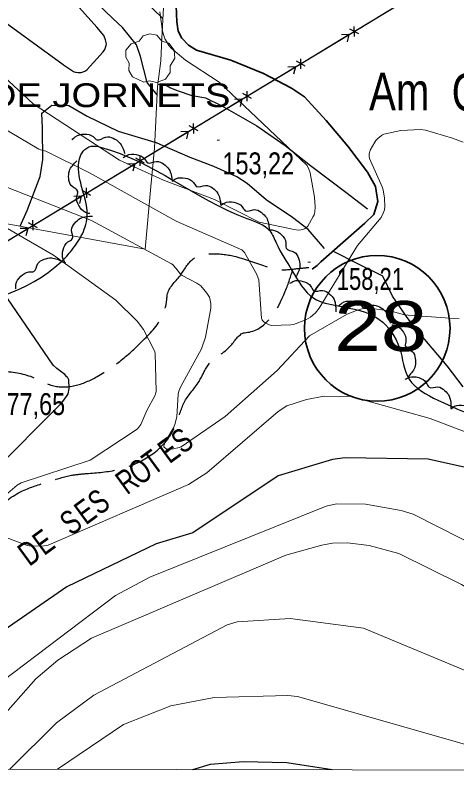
# Model space of a CAD drawing. Extents: x 483840 to 488445, y 4386047 to 4389027.
# Drawn here: x 484181.3 to 484357.8, y 4386444.9 to 4386749.2 of the extents above; entities that cross this region are included whole.
import ezdxf
from ezdxf.enums import TextEntityAlignment as Align

# ---------------------------------------------------------------- set-up
doc = ezdxf.new("R2010")
doc.units = 0
doc.header["$LTSCALE"] = 4
doc.linetypes.add('LONG_DASHED', pattern=[7.5, 6, -1.5])
for name, color, linetype, lineweight in [('1', 7, 'Continuous', 13), ('13', 7, 'Continuous', 25), ('25', 7, 'LONG_DASHED', 25), ('27', 7, 'Continuous', 25), ('29', 7, 'Continuous', 13), ('38', 7, 'Continuous', 25), ('43', 7, 'Continuous', 25), ('51', 7, 'Continuous', 13), ('6', 7, 'Continuous', 35), ('7', 7, 'Continuous', 13), ('8', 7, 'Continuous', 25), ('9', 7, 'Continuous', 13)]:
    doc.layers.add(name, color=color, linetype=linetype, lineweight=lineweight)
doc.layers.add('31', color=7, linetype='Continuous')
doc.layers.add('5', color=7, linetype='Continuous')

msp = doc.modelspace()

# ---------------------------------------------------------------- linework, layer by layer
at = {"layer": '1'}
msp.add_lwpolyline([(484110.5, 4388760.3), (487685.8, 4388753.5), (487681.9, 4386441.2), (484105.5, 4386448.1)], close=True, dxfattribs=at)
at = {"layer": '25'}
for points in [[(484238.11, 4386717.41), (484234.09, 4386722.37), (484231.36, 4386732.68), (484229.87, 4386737.33), (484224.27, 4386744.27), (484220.31, 4386747.9), (484213.85, 4386754.21)], [(484232.46, 4386755.62), (484240.38, 4386747.89)], [(484238.38, 4386721.61), (484241.44, 4386721.36), (484243.45, 4386720.19), (484246.51, 4386718.94), (484251.48, 4386717.25), (484257.46, 4386716.23), (484263.97, 4386712.97), (484277.97, 4386704.98), (484289.18, 4386697.18), (484299.41, 4386689.13), (484313.97, 4386678.15), (484322.22, 4386671.82)], [(484183.27, 4386664.84), (484186.06, 4386671.21), (484191.27, 4386684.79), (484192.36, 4386691.58), (484192.2, 4386704.04), (484192.02, 4386710.01), (484196, 4386713.23), (484202.78, 4386713.14), (484210.15, 4386708.79), (484222.46, 4386702.83), (484237.13, 4386698.45)], [(484304.96, 4386655.92), (484298.47, 4386663.58), (484292.2, 4386668.41), (484281.64, 4386675.45), (484274.11, 4386681.95), (484269.92, 4386684.63), (484260.73, 4386688.69), (484251.28, 4386692.36), (484237.13, 4386698.45)], [(484360.41, 4386600.63), (484354.02, 4386609.13), (484342.83, 4386622.33), (484338.08, 4386628.43), (484332.17, 4386636.95), (484328.3, 4386644.98), (484318.53, 4386649.68), (484308.26, 4386654.85)]]:
    msp.add_lwpolyline(points, dxfattribs=at)
at = {"layer": '27'}
for points in [[(484204.1, 4386699.4), (484205.36, 4386700.65), (484209, 4386701.71), (484212.54, 4386700.67), (484214.12, 4386699.36), (484217.48, 4386700.52), (484220.43, 4386700.06), (484222.95, 4386698.39), (484225.09, 4386693.91)], [(484109.46, 4386593.06), (484150.94, 4386626.49), (484199.73, 4386650.7), (484203.95, 4386655.31), (484208.18, 4386661.85), (484210.1, 4386669.53), (484207.03, 4386691.82), (484208.56, 4386694.9), (484211.64, 4386696.82), (484215.48, 4386696.43), (484273.86, 4386668), (484283.08, 4386663), (484285.77, 4386658), (484291.92, 4386647.24), (484300.75, 4386636.1), (484310.35, 4386633.02), (484326.87, 4386627.64), (484334.94, 4386616.12), (484338.78, 4386603.82), (484350.3, 4386595.36), (484426.74, 4386553.47), (484429.82, 4386547.71), (484429.82, 4386545.79), (484429.82, 4386540.02), (484422.52, 4386535.03), (484386.41, 4386496.98), (484386.03, 4386493.91), (484387.56, 4386490.45), (484397.55, 4386477), (484431.35, 4386465.85), (484447.87, 4386459.7), (484460.55, 4386449.71), (484465.92, 4386445.87)], [(484224.46, 4386692.17), (484225.93, 4386693.16), (484229.71, 4386693.52), (484232.99, 4386691.84), (484234.3, 4386690.25), (484237.82, 4386690.77), (484240.63, 4386689.76), (484242.79, 4386687.65), (484244.06, 4386682.86)], [(484211.11, 4386669.9), (484209.41, 4386670.41), (484206.74, 4386673.11), (484205.96, 4386676.71), (484206.36, 4386678.73), (484203.73, 4386681.13), (484202.73, 4386683.94), (484202.99, 4386686.95), (484205.9, 4386690.97)], [(484244.07, 4386682.88), (484245.56, 4386683.85), (484249.34, 4386684.12), (484252.59, 4386682.38), (484253.87, 4386680.77), (484257.4, 4386681.21), (484260.19, 4386680.15), (484262.31, 4386677.99), (484263.48, 4386673.17)], [(484263.48, 4386673.18), (484264.97, 4386674.15), (484268.76, 4386674.43), (484272.01, 4386672.68), (484273.28, 4386671.07), (484276.81, 4386671.51), (484279.6, 4386670.45), (484281.72, 4386668.3), (484282.89, 4386663.48)], [(484201.42, 4386650.13), (484200.54, 4386651.67), (484200.49, 4386655.47), (484202.43, 4386658.61), (484204.11, 4386659.79), (484203.89, 4386663.33), (484205.11, 4386666.06), (484207.39, 4386668.04), (484212.27, 4386668.92)], [(484282.73, 4386663.35), (484284.51, 4386663.33), (484287.8, 4386661.45), (484289.53, 4386658.18), (484289.69, 4386656.14), (484292.86, 4386654.53), (484294.59, 4386652.1), (484295.15, 4386649.13), (484293.43, 4386644.47)], [(484181.61, 4386639.79), (484181.64, 4386641.56), (484183.51, 4386644.86), (484186.77, 4386646.59), (484188.82, 4386646.75), (484190.42, 4386649.93), (484192.85, 4386651.66), (484195.82, 4386652.22), (484200.48, 4386650.51)], [(484291.08, 4386642.08), (484292.65, 4386642.91), (484296.45, 4386642.84), (484299.53, 4386640.81), (484300.65, 4386639.09), (484304.2, 4386639.21), (484306.89, 4386637.9), (484308.8, 4386635.56), (484309.53, 4386630.66)], [(484310.61, 4386633.01), (484311.95, 4386634.18), (484315.65, 4386635), (484319.12, 4386633.74), (484320.61, 4386632.33), (484324.04, 4386633.27), (484326.95, 4386632.63), (484329.36, 4386630.8), (484331.21, 4386626.19)], [(484331.9, 4386625.49), (484333.64, 4386625.1), (484336.49, 4386622.6), (484337.52, 4386619.06), (484337.27, 4386617.02), (484340.05, 4386614.81), (484341.25, 4386612.08), (484341.2, 4386609.05), (484338.59, 4386604.84)], [(484337.24, 4386603.7), (484338.83, 4386604.51), (484342.62, 4386604.39), (484345.67, 4386602.31), (484346.77, 4386600.57), (484350.32, 4386600.64), (484352.99, 4386599.29), (484354.87, 4386596.93), (484355.53, 4386592.01)], [(484355.5, 4386591.93), (484356.98, 4386592.9), (484360.76, 4386593.19), (484364.02, 4386591.46), (484365.3, 4386589.85), (484368.83, 4386590.31), (484371.62, 4386589.26), (484373.75, 4386587.11), (484374.94, 4386582.3)]]:
    msp.add_spline(points, degree=3, dxfattribs=at)
at = {"layer": '29'}
msp.add_lwpolyline([(484232.72, 4386722.39), (484228.18, 4386724.51), (484226.77, 4386727.05), (484226.87, 4386730.03), (484225.5, 4386732.44), (484225.54, 4386735.19), (484227.7, 4386737.79), (484230.89, 4386738.79), (484232.54, 4386740.98), (484235.11, 4386741.81), (484237.97, 4386741.16), (484239.92, 4386738.89), (484242.73, 4386738.07), (484244.86, 4386735.22), (484245.1, 4386732.09), (484243.22, 4386728.94), (484243.22, 4386726.26), (484241.4, 4386723.65), (484237.78, 4386722.31), (484235.01, 4386722.94)], close=True, dxfattribs=at)
at = {"layer": '38', "linetype": 'LONG_DASHED'}
for points in [[(484105.83, 4386602.86), (484120.25, 4386605.97), (484125.44, 4386607.52), (484142.42, 4386608.61), (484158.29, 4386608.6), (484166.82, 4386608.16), (484175, 4386607.19), (484187.39, 4386604.89), (484196.18, 4386601.23), (484205.17, 4386601.18), (484214.03, 4386604.78), (484224.32, 4386611.82), (484233.03, 4386619.81), (484240.78, 4386630.51), (484241.97, 4386636.1), (484242.13, 4386637.47), (484247.21, 4386645.1), (484252.45, 4386651.78), (484259.96, 4386653.86), (484269.47, 4386652.73), (484282.11, 4386648.69), (484286.84, 4386647.57), (484294.44, 4386647.98), (484297.24, 4386648.27), (484298.7, 4386648.44)], [(484123.13, 4386448.07), (484125.81, 4386455.66), (484130.34, 4386466.29), (484135.12, 4386475.21), (484140.67, 4386482.44), (484146.71, 4386488.67), (484151.76, 4386493.23), (484160.57, 4386502.39), (484175.16, 4386517.6), (484175.01, 4386533.08), (484172.55, 4386548.25), (484174.22, 4386551.28), (484184.97, 4386559.42), (484194.87, 4386562.88), (484203.87, 4386565.35), (484209.79, 4386566.03), (484222.61, 4386567.68), (484231.83, 4386571.16), (484241.23, 4386578.42), (484245.83, 4386586.17), (484249.16, 4386594.97), (484254.8, 4386602.85), (484258.7, 4386609.69), (484267.56, 4386617.19), (484273.47, 4386622.4), (484273.64, 4386622.41), (484289.31, 4386638.91), (484292.37, 4386647.77)]]:
    msp.add_spline(points, degree=3, dxfattribs=at)
at = {"layer": '43'}
for p, q in [((484319.03, 4386744.02), (484336.16, 4386754.35)), ((484318.64, 4386741.75), (484315.14, 4386743.68)), ((484316.93, 4386740.72), (484316.86, 4386744.72)), ((484297.62, 4386731.1), (484314.75, 4386741.43)), ((484314.75, 4386741.43), (484311.75, 4386741.38)), ((484314.75, 4386741.43), (484314.03, 4386738.52)), ((484295.53, 4386727.81), (484295.45, 4386731.8)), ((484276.22, 4386718.19), (484293.34, 4386728.52)), ((484293.34, 4386728.52), (484290.34, 4386728.46)), ((484293.34, 4386728.52), (484292.62, 4386725.61)), ((484297.24, 4386728.84), (484293.74, 4386730.77)), ((484275.83, 4386715.93), (484272.33, 4386717.86)), ((484274.12, 4386714.89), (484274.04, 4386718.89)), ((484254.81, 4386705.28), (484271.93, 4386715.61)), ((484271.93, 4386715.61), (484268.93, 4386715.55)), ((484271.93, 4386715.61), (484271.21, 4386712.7)), ((484254.42, 4386703.01), (484250.92, 4386704.94)), ((484252.71, 4386701.98), (484252.64, 4386705.98)), ((484233.4, 4386692.37), (484250.53, 4386702.7)), ((484250.53, 4386702.7), (484247.53, 4386702.64)), ((484250.53, 4386702.7), (484249.81, 4386699.79)), ((484233.02, 4386690.1), (484229.52, 4386692.03)), ((484231.3, 4386689.07), (484231.23, 4386693.06)), ((484212, 4386679.45), (484229.12, 4386689.78)), ((484229.12, 4386689.78), (484226.12, 4386689.73)), ((484229.12, 4386689.78), (484228.4, 4386686.87)), ((484209.9, 4386676.16), (484209.82, 4386680.15)), ((484190.59, 4386666.54), (484207.71, 4386676.87)), ((484207.71, 4386676.87), (484204.71, 4386676.81)), ((484207.71, 4386676.87), (484206.99, 4386673.96)), ((484211.61, 4386677.19), (484208.11, 4386679.12)), ((484190.2, 4386664.28), (484186.7, 4386666.21)), ((484188.49, 4386663.24), (484188.42, 4386667.24)), ((484169.18, 4386653.63), (484186.31, 4386663.96)), ((484186.31, 4386663.96), (484183.31, 4386663.9)), ((484186.31, 4386663.96), (484185.59, 4386661.05))]:
    msp.add_line(p, q, dxfattribs=at)
msp.add_lwpolyline([(484106.12, 4386615.59), (484337.37, 4386755.08), (484652.95, 4386942.58)], dxfattribs=at)
at = {"layer": '51'}
msp.add_lwpolyline([(484248.51, 4386849.6), (484241.33, 4386764.8), (484239.92, 4386739.91), (484239.51, 4386731.03), (484238.27, 4386720.73), (484237, 4386696.09), (484235.58, 4386680.73), (484233.32, 4386655.65), (484139.5, 4386672.88), (484106, 4386679.36)], dxfattribs=at)
at = {"layer": '6'}
msp.add_lwpolyline([(484300.09, 4386647.65), (484302.08, 4386649.19), (484303.54, 4386650.68), (484321.03, 4386666.13), (484324.65, 4386669.6), (484326.31, 4386674.79), (484325.39, 4386680.77), (484322.18, 4386686.43), (484314.3, 4386696.8), (484305.64, 4386707.18), (484296.98, 4386716.58), (484291.77, 4386720.05), (484280.55, 4386725.85), (484267.47, 4386731.29), (484253.74, 4386735.26), (484250.57, 4386737.27), (484247.98, 4386740.02), (484246.52, 4386742.77), (484245.89, 4386746.56), (484245.72, 4386752.89), (484247.25, 4386775.93), (484249.67, 4386808.2), (484252.03, 4386836.16), (484254.14, 4386854.36)], dxfattribs=at)
msp.add_circle((484326.04, 4386624.07), 29.1, dxfattribs=at)
at = {"layer": '7'}
for p, q in [((484262.02, 4386699.33), (484263.02, 4386699.33)), ((484298.33, 4386650.53), (484299.33, 4386650.53))]:
    msp.add_line(p, q, dxfattribs=at)
at = {"layer": '8'}
for points in [[(484171.45, 4386750.58), (484200.54, 4386729.47), (484200.6, 4386729.4), (484204.66, 4386726.77), (484205.3, 4386726.5), (484205.66, 4386726.39), (484206.32, 4386726.27), (484207.26, 4386726.25), (484207.76, 4386726.32), (484208.49, 4386726.53), (484209.42, 4386727), (484210.14, 4386727.5), (484216.44, 4386734.54), (484217.12, 4386735.55), (484217.72, 4386737.03), (484217.75, 4386737.16), (484217.78, 4386737.72), (484217.74, 4386738.28), (484217.46, 4386739.38), (484217.02, 4386740.48), (484216.72, 4386741.04), (484213.94, 4386744.37), (484213.9, 4386744.4), (484204.65, 4386754.79)], [(484171.36, 4386565.64), (484199.95, 4386594.31), (484202.1, 4386597.21), (484202.46, 4386597.89), (484202.94, 4386599.99), (484202.94, 4386600.01), (484202.76, 4386603.46), (484202.75, 4386603.47), (484202.18, 4386604.49), (484202, 4386604.73), (484201.2, 4386605.56), (484198.02, 4386607.98), (484196.52, 4386609.41), (484178.33, 4386635.85)], [(484363.67, 4386567.9), (484346.43, 4386571.82), (484313.27, 4386572.3), (484308.22, 4386571.64), (484286.41, 4386565.1)], [(484286.41, 4386565.1), (484252.34, 4386542.35), (484237.64, 4386537.94), (484201.9, 4386520.77), (484153.46, 4386487.32)], [(484252.4, 4386447.82), (484259.4, 4386449.88), (484272.41, 4386450.97), (484289.85, 4386450.63), (484308.07, 4386447.71)]]:
    msp.add_lwpolyline(points, dxfattribs=at)
at = {"layer": '9'}
for points in [[(484295.64, 4386663.41), (484294.53, 4386663.31), (484292.84, 4386663.5), (484278.8, 4386666.51), (484260.96, 4386675.56), (484240.55, 4386683.22), (484223.03, 4386691.25), (484188.53, 4386713.84), (484174.7, 4386726.58), (484138.31, 4386753.02), (484106.2, 4386770.2)], [(484239.2, 4386750.59), (484240.25, 4386742.88), (484241.2, 4386739.78), (484241.29, 4386739.57), (484242.77, 4386737.13), (484243.73, 4386736.06), (484249.45, 4386731.19), (484262.81, 4386722.43), (484297.85, 4386689.23), (484298.52, 4386688.01), (484299.23, 4386686.19), (484301.01, 4386676.49), (484301.26, 4386672.64), (484301.04, 4386670.53), (484300.78, 4386669.46), (484300.48, 4386668.75), (484298.37, 4386664.96), (484297.92, 4386664.48), (484297.4, 4386664.08), (484296.95, 4386663.83), (484296.2, 4386663.53), (484295.64, 4386663.41)], [(484156.91, 4386715.61), (484190.82, 4386695.63), (484191.46, 4386695.36), (484193.61, 4386694.82), (484210.96, 4386686.19), (484245.7, 4386666.91), (484271.9, 4386655.39), (484272.96, 4386654.31), (484277.95, 4386645.6), (484278.51, 4386644.18), (484278.74, 4386643.41), (484279.83, 4386628.06), (484280.08, 4386627.44), (484280.28, 4386627.12), (484280.76, 4386626.62), (484281.48, 4386626.09), (484282.29, 4386625.68), (484283.27, 4386625.33), (484283.84, 4386625.2), (484291.5, 4386625.41), (484292.57, 4386625.56), (484297.57, 4386627.51), (484299.34, 4386628.59), (484301.33, 4386630.28), (484302.85, 4386632.09), (484318.11, 4386657.13), (484327.58, 4386668.41), (484328.46, 4386670.09), (484328.9, 4386671.39), (484329.03, 4386672.61), (484328.94, 4386676.02), (484328.37, 4386679.35), (484328.02, 4386680.66), (484322.96, 4386691.97), (484322.83, 4386692.67), (484322.8, 4386693.06), (484322.85, 4386693.76), (484323.04, 4386694.73), (484323.21, 4386695.25), (484325.03, 4386698.53), (484325.47, 4386699.14), (484326.27, 4386699.99), (484327.73, 4386701.13), (484328.11, 4386701.37), (484328.75, 4386701.7), (484335.47, 4386703.1), (484343.31, 4386703.49), (484345.34, 4386703.32), (484356.07, 4386700.09), (484360.43, 4386698.46)], [(484173.75, 4386682.09), (484211.88, 4386667.19), (484243.83, 4386649.83), (484244.42, 4386649.38), (484244.42, 4386649.37), (484244.44, 4386649.36), (484245.58, 4386648.14), (484247.42, 4386645.78), (484248.01, 4386645.24), (484253.89, 4386642.13), (484255.58, 4386640.99), (484257.95, 4386638.15), (484258.93, 4386636.59), (484258.93, 4386636.57), (484258.94, 4386636.56), (484259.28, 4386635.39), (484259.52, 4386634), (484259.59, 4386632.15), (484257.34, 4386620.58), (484255.74, 4386615.94), (484247.53, 4386600.88), (484246.79, 4386598.92), (484246.52, 4386597.82), (484245.93, 4386588.75), (484245.13, 4386585.66), (484244.55, 4386584.28), (484241.34, 4386578.66), (484240.93, 4386577.53), (484240.79, 4386576.92), (484240.73, 4386576.77), (484240.79, 4386576.66), (484241.62, 4386575.9), (484241.75, 4386575.8), (484241.88, 4386575.75), (484244.57, 4386575.91), (484246.89, 4386576.44), (484247.63, 4386576.69), (484265.31, 4386588.87), (484286.08, 4386607.2), (484299.02, 4386621.07), (484313.79, 4386629.59), (484318.01, 4386631.35), (484319.98, 4386631.86), (484323.89, 4386632.02), (484331.57, 4386630.92), (484336.99, 4386629.51), (484338.47, 4386629.29), (484358.75, 4386627.92)], [(484178.43, 4386558.14), (484182.14, 4386561.34), (484183.73, 4386562.3), (484211.31, 4386571.44), (484230.08, 4386583.82), (484230.8, 4386584.58), (484231.58, 4386585.61), (484233.98, 4386591.25), (484237.22, 4386597.35), (484237.43, 4386597.95), (484237.63, 4386598.88), (484237.28, 4386614.16), (484236.97, 4386615.03), (484232.6, 4386623.57), (484230.06, 4386626.98), (484221.61, 4386635.37), (484196.69, 4386653.29), (484155.55, 4386677.08)], [(484374.77, 4386577.51), (484347.24, 4386588.08), (484315.69, 4386596.8), (484304.8, 4386596.95), (484297.8, 4386595.67), (484289.85, 4386593.07), (484286.44, 4386590.83), (484257.94, 4386566.32), (484250.63, 4386561.68)], [(484250.63, 4386561.68), (484194.56, 4386537.4), (484192.92, 4386537.15), (484187.67, 4386536.97), (484186.13, 4386537.24), (484175.92, 4386541.13)], [(484143.24, 4386448.03), (484144.73, 4386448.77), (484161.44, 4386465.03), (484176.34, 4386483.25), (484221.45, 4386517.27), (484235.16, 4386524.61), (484305.66, 4386553), (484309.72, 4386553.93), (484321.3, 4386553.85), (484335.62, 4386551.25), (484340.44, 4386549.87), (484407.12, 4386515.96), (484412.52, 4386512.39), (484428.24, 4386507.63), (484438.05, 4386505.61), (484438.79, 4386505.37), (484440.5, 4386504.45), (484441.58, 4386503.17), (484443.37, 4386500.11)], [(484157.47, 4386448), (484159.38, 4386449.87), (484189.58, 4386483.98), (484198.35, 4386491.47), (484211.81, 4386500.24), (484289.55, 4386533.44), (484303.86, 4386537.4), (484308.13, 4386538.16), (484314.22, 4386538.31), (484322.79, 4386537.25), (484334.66, 4386534.14), (484359.78, 4386521.76), (484382.51, 4386507.78), (484396.76, 4386494.23), (484399.16, 4386492.54)], [(484585.35, 4386447.17), (484571.82, 4386453.51), (484543.8, 4386461.31), (484501.29, 4386466.52), (484448.74, 4386458.82), (484441.24, 4386459.42), (484387.93, 4386468.88), (484386.11, 4386469.88), (484361.22, 4386487.35), (484320.5, 4386504.22), (484291.24, 4386508.06), (484269.99, 4386506.78), (484266.07, 4386505.63), (484212.71, 4386477.42), (484197.86, 4386466.42), (484179.22, 4386447.96)], [(484378.75, 4386447.57), (484373.39, 4386451.42), (484360.91, 4386457.85), (484294.23, 4386477.01), (484290.34, 4386477.36), (484260.85, 4386476.52), (484243.58, 4386473.23), (484224.58, 4386465.82), (484198.25, 4386447.92)]]:
    msp.add_lwpolyline(points, dxfattribs=at)

# ---------------------------------------------------------------- texts
at = {"layer": '13', "width": 1.25}
msp.add_text('28', height=20, dxfattribs=at).set_placement((484327.47, 4386614.98), align=Align.CENTER)
at = {"layer": '31', "width": 0.8}
for s, p in [('Am', (484334.84, 4386711.21)), ('Ga', (484366.52, 4386710.94))]:
    msp.add_text(s, height=15, dxfattribs=at).set_placement(p, align=Align.CENTER)
at = {"layer": '5', "width": 1.2}
msp.add_text('OLIVAR DE JORNETS', height=9.5, dxfattribs=at).set_placement((484110.65, 4386712.47))
at = {"layer": '5', "width": 0.75}
for s, rotation, p in [('S', 36.556, (484250.84, 4386575.47)), ('E', 36.221, (484245.52, 4386571.57)), ('T', 36.221, (484239, 4386566.79)), ('O', 36.221, (484234.09, 4386563.18)), ('R', 36.221, (484228.8, 4386559.32)), ('S', 36.221, (484217.45, 4386551)), ('E', 36.221, (484212.12, 4386547.1)), ('S', 36.221, (484206.31, 4386542.85)), ('E', 36.221, (484195.42, 4386534.87)), ('D', 36.221, (484189.74, 4386530.72))]:
    msp.add_text(s, height=9.49, rotation=rotation, dxfattribs=at).set_placement(p, align=Align.CENTER)
at = {"layer": '7'}
for s, width, p in [('153,22', 0.8, (484264.18, 4386685.62)), ('158,21', 0.75, (484309.89, 4386639.43)), ('177,65', 0.8, (484172.66, 4386589.42))]:
    msp.add_text(s, height=8.75, dxfattribs=dict(at, width=width)).set_placement(p)

doc.saveas('drawing.dxf')
